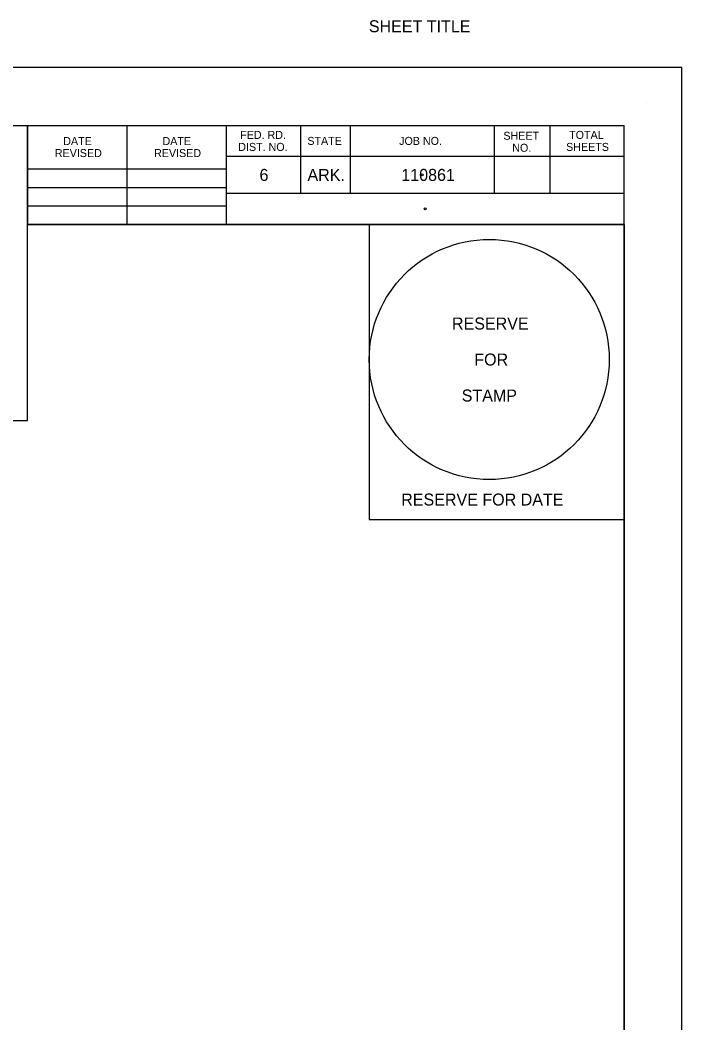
# Model space of a CAD drawing. Extents: x 0 to 19, y -0.6 to 11.2.
# Drawn here: x 13.69 to 17, y 6.22 to 11.24 of the extents above; entities that cross this region are included whole.
import ezdxf

# ---------------------------------------------------------------- set-up
doc = ezdxf.new("R2010")
doc.units = 0
for name, color, linetype in [('G-ANNO-TEXT', 7, 'Continuous'), ('G-Border-Paper', 7, 'Continuous'), ('G-Border-Sheet', 7, 'Continuous'), ('G-No Plot-Anchor', 7, 'Continuous'), ('G-No Plot-Border-1', 7, 'Continuous'), ('G-No Plot-Border-2', 7, 'Continuous'), ('G-No Plot-Stamp-1', 7, 'Continuous'), ('G-Table-Major', 7, 'Continuous'), ('G-Table-Minor', 7, 'Continuous')]:
    doc.layers.add(name, color=color, linetype=linetype)

msp = doc.modelspace()

# ---------------------------------------------------------------- linework, layer by layer
at = {"layer": 'G-ANNO-TEXT'}
msp.add_line((16.821, 10.8269), (16.821, 10.8269), dxfattribs=at)
at = {"layer": 'G-Border-Paper'}
msp.add_lwpolyline([(17, 11), (0, 11), (0, 0), (17, 0)], close=True, dxfattribs=at)
at = {"layer": 'G-Border-Sheet'}
for p in [(0.758, 10.7116), (16.7116, 0.2884)]:
    msp.add_line(p, (16.7116, 10.7116), dxfattribs=at)
at = {"layer": 'G-No Plot-Anchor'}
for centre in [(15.7013, 10.4639), (15.7161, 10.2941)]:
    msp.add_circle(centre, 0.005, dxfattribs=at)
at = {"layer": 'G-No Plot-Border-1'}
msp.add_lwpolyline([(0.758, 5.4354), (0.758, 10.7116), (13.7281, 10.7116), (13.7281, 10.2161), (14.7206, 10.2161), (14.8974, 10.2161), (15.4366, 10.2161), (15.4366, 8.7411), (16.7116, 8.7411), (16.7116, 5.4354)], close=True, dxfattribs=at)
at = {"layer": 'G-No Plot-Border-2'}
msp.add_lwpolyline([(0.758, 5.4354), (0.758, 10.7116), (12.4531, 10.7116), (12.4531, 9.2366), (13.7281, 9.2366), (13.7281, 10.2161), (16.7116, 10.2161), (16.7116, 5.4354)], close=True, dxfattribs=at)
at = {"layer": 'G-No Plot-Stamp-1'}
msp.add_circle((16.0366, 9.5411), 0.6, dxfattribs=at)
at = {"layer": 'G-Table-Major'}
for p, q in [((13.7281, 10.2168), (13.7281, 10.7116)), ((14.7206, 10.7116), (14.7206, 10.2161)), ((13.7281, 10.4946), (14.7206, 10.4946)), ((16.7116, 10.2161), (13.7281, 10.2161))]:
    msp.add_line(p, q, dxfattribs=at)
at = {"layer": 'G-Table-Minor'}
for p, q in [((14.2256, 10.2165), (14.2256, 10.7116)), ((15.0926, 10.7116), (15.0926, 10.3716)), ((15.3411, 10.7116), (15.3411, 10.3716)), ((16.0616, 10.7116), (16.0616, 10.3716)), ((16.3396, 10.7116), (16.3396, 10.3716)), ((16.7116, 10.5561), (14.7206, 10.5561)), ((16.7116, 10.5656), (16.7116, 10.5656)), ((13.7281, 10.4011), (14.7206, 10.4011)), ((16.7116, 10.3716), (14.7206, 10.3716)), ((13.7281, 10.3096), (14.7206, 10.3096))]:
    msp.add_line(p, q, dxfattribs=at)

# ---------------------------------------------------------------- texts
at = {"layer": 'G-ANNO-TEXT'}
for s, height, p in [('SHEET TITLE', 0.06, (15.4345, 11.1771)), ('FED. RD.', 0.04, (14.7913, 10.6439)), ('SHEET', 0.04, (16.1072, 10.6396)), ('TOTAL', 0.04, (16.4361, 10.6439)), ('DATE', 0.04, (13.9066, 10.6131)), ('DATE', 0.04, (14.4029, 10.6131)), ('STATE', 0.04, (15.1271, 10.6139)), ('JOB NO.', 0.04, (15.5861, 10.6139)), ('REVISED', 0.04, (13.8646, 10.5531)), ('REVISED', 0.04, (14.3608, 10.5531)), ('DIST. NO.', 0.04, (14.7816, 10.5839)), ('NO.', 0.04, (16.1515, 10.5796)), ('SHEETS', 0.04, (16.421, 10.5839)), ('6', 0.06, (14.8879, 10.4339)), ('ARK.', 0.06, (15.1276, 10.4339)), ('110861', 0.06, (15.5969, 10.4339))]:
    msp.add_text(s, height=height, dxfattribs=at).set_placement(p)
at = {"layer": 'G-No Plot-Stamp-1'}
for s, p in [('RESERVE', (15.85, 9.6911)), ('FOR ', (15.9617, 9.5111)), ('STAMP', (15.8989, 9.3311)), ('RESERVE FOR DATE', (15.5963, 8.8111))]:
    msp.add_text(s, height=0.06, dxfattribs=at).set_placement(p)

doc.saveas('drawing.dxf')
